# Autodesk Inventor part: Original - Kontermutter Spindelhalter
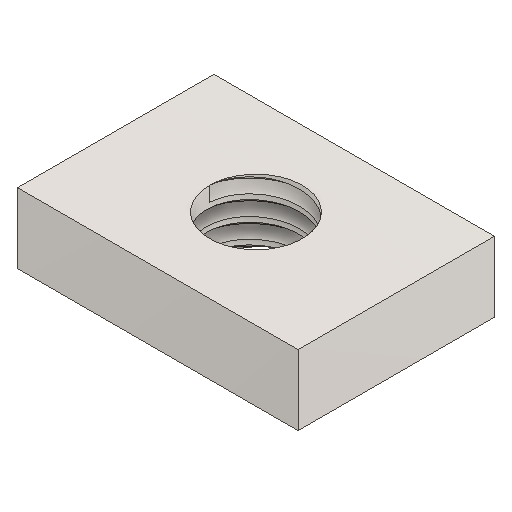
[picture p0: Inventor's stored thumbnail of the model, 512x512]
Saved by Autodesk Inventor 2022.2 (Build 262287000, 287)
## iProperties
Created: 2024-09
Part Number: Original - Kontermutter Spindelhalter
Material: Generico
Document SubType Name: Modeling
Designer: 18907419
Density: 1 g/cm^3
Appearance: Default
Author: 18907419
Revision Number: ANY
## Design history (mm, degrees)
feature "Gewinde1"
node "Solido1"
